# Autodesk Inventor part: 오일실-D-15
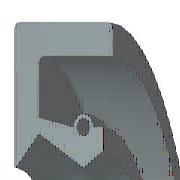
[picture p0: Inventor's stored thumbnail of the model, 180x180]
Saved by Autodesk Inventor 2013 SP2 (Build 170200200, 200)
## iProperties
IsCustomPart: 0
Company: 한국ATC센터
Created: 2014-12
Part Number: 오일실-D-15
Material: 고무
Description: 오일-실
Document SubType Name: Modeling
Standard: KS B 2804
Designer: KYOUNG IL JANG
Standards Organization: KS
Language: ko-KR
Size Designation: D - 15 30 7
Categories: <MemberInstance><Categories><Category DisplayName="샤프트 부품" InternalName="7f7aeb1f-a693-4053-b835-cee3144e0d98" Mnemonic="SHFT"><Category DisplayName="실링" Intern
Density: 0.93 g/cm^3
Mass: 1.95008 g
Surface Area: 27.8517 cm^2
Volume: 2.09686 cm^3
Author: KYOUNG IL JANG
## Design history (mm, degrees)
revolve "본체" stored, may be unused: angle "d17" = 90 deg
revolve "스프링1" stored, may be unused: angle "d18" = 90 deg
body "Solid1"
sketch "스케치1"
  geometry: L1 (0, 15)-(7, 15); L2 (7, 13.25)-(1.75, 13.25); L3 (1.75, 9.25)-(4.9, 7.5); L4 (4.9, 7.5)-(0, 7.5); L5 (0, 0)-(9.586, 0) reference; L6 (4.9, 7.5)-(6.3, 8.375); L7 (0, 18)-(0, -3) reference; L8 (-1.941, 0)-(11.507, 0) reference; L9 (4.2, 9.6)-(1.75, 10.09); L10 (1.75, 10.09)-(1.75, 13.25); L11 (0, 15)-(0, 7.588); L12 (4.9, 7.5)-(0, 7.5); L13 (1.75, 9.25)-(0.152, 7.528); L14 (7, 15)-(7, 13.25); L15 (5.6, 9.6)-(6.3, 9.6); L16 (6.3, 9.6)-(6.3, 8.375); C1 r 0.455 at (4.9, 9.6); A1 r 0.7 centre (4.9, 9.6) between (5.6, 9.6) and (4.2, 9.6); A2 r 0.088 centre (0.088, 7.588) between (0, 7.588) and (0.152, 7.528); 1 further point
  constraints: 28 end point, 5 horizontal alignment, 5 point on line, 4 point on circle, 4 vertical alignment, 3 centre point, 3 tangent, 2 collinear, 2 horizontal, 2 perpendicular, 1 coincident, 1 parallel
  dimensions: "d0" = 30 diameter of L1 L5 (= SD2); "d1" = 1.75 distance of L1.end L2.start (= SD); "d2" = 0.91 diameter of C1 (= SPDI); "d3" = 1.4 diameter of A1 (= SPDA); "d4" = 15 diameter of L3.end L5 (= NND); "d5" = 18.5 diameter of L3.start L5 (= TKDM); "d7" = 20.18 diameter of L9.end L5 (= TKDM + 0.24 x SWDT); "d8" = 1.75 distance between parallel lines of L11 L10 (= SD); "d9" = 4.9 distance from line of L11 C1.centre (= SPDST); "d10" = 19.2 diameter of C1.centre L5 (= HLDM); "d11" = 0.0875 radius of A2 (= 0.25 x LAB); "d12" = 6.3 distance between parallel lines of L11 L16 (= SDI); "d13" = 16.75 diameter of L6.end L5 (= ABDM); "d14" = 7 distance from line of L11 L1.end (= SWDT)
fillet "모깎기1" dims "d6" = 0.3 (= RR)
other parameters: "SD2" = 30 [user parameter; used in 1 equation term], "SWDT" = 7 [user parameter; used in 2 equation terms], "RR" = 0.3 [user parameter; used in 1 equation term], "SD" = 1.75 [user parameter; used in 2 equation terms], "NND" = 15 [user parameter; used in 1 equation term], "SPDA" = 1.4 [user parameter; used in 1 equation term], "SPDI" = 0.91 [user parameter; used in 1 equation term], "TKDM" = 18.5 [user parameter; used in 2 equation terms], "HLDM" = 19.2 [user parameter; used in 1 equation term], "ABDM" = 16.75 [user parameter; used in 1 equation term], "SDI" = 6.3 [user parameter; used in 1 equation term], "SPDST" = 4.9 [user parameter; used in 1 equation term], "LAB" = 0.35 [user parameter; used in 1 equation term], "d15" = 0, "d16" = 0, "d19" = 0
